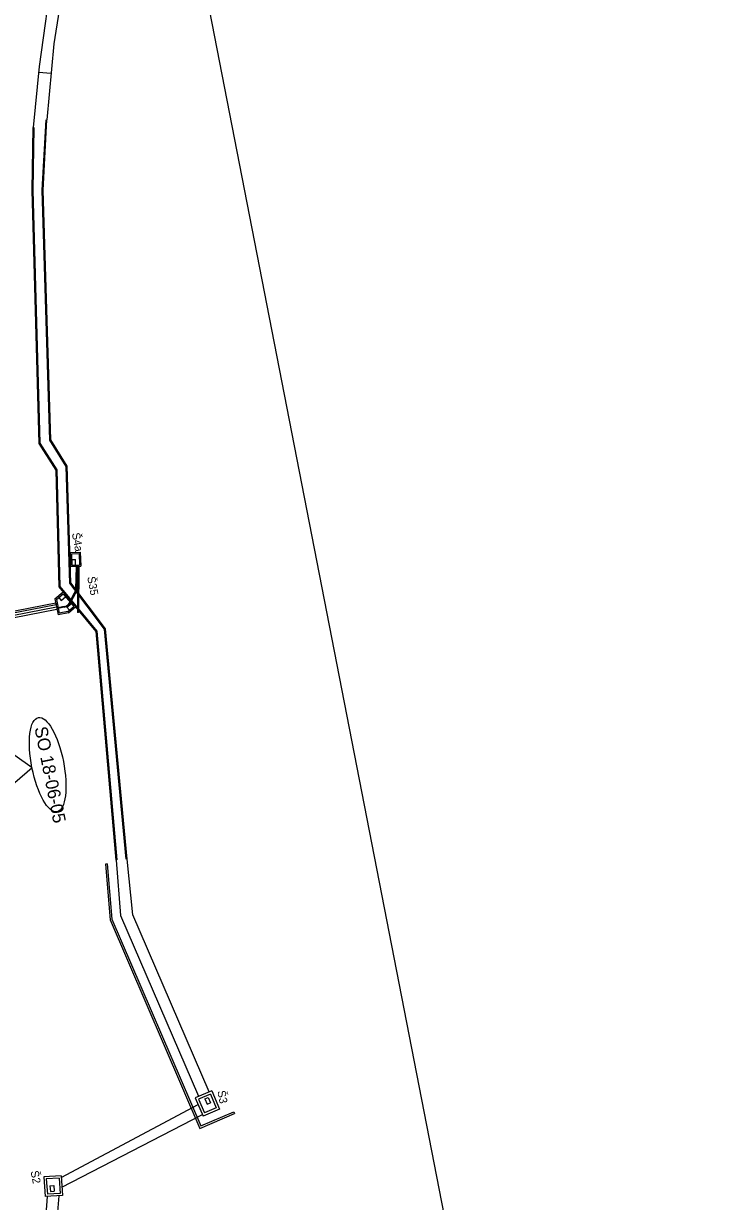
# Model space of a CAD drawing. Extents: x -545258 to -544992, y -1122311 to -1121664.
# Drawn here: x -545101.7 to -544992, y -1122054.6 to -1121870.6 of the extents above; entities that cross this region are included whole.
import ezdxf

# ---------------------------------------------------------------- set-up
doc = ezdxf.new("R2010")
doc.units = 0
for name, color, linetype in [('SO18-15-08_def', 7, 'Continuous'), ('SO18-15-15', 7, 'Continuous'), ('SOPS', 7, 'Continuous'), ('Vrstva 10', 7, 'Continuous')]:
    doc.layers.add(name, color=color, linetype=linetype)

msp = doc.modelspace()

# ---------------------------------------------------------------- linework, layer by layer
at = {"layer": 'SO18-15-08_def'}
for p, q in [((-545097.39, -1121878.4), (-545099.34, -1121878.23)), ((-545094.42, -1121953.24), (-545092.82, -1121953.19)), ((-545094.42, -1121953.24), (-545094.35, -1121955.44)), ((-545094.21, -1121953.44), (-545093.01, -1121953.4)), ((-545094.21, -1121953.44), (-545094.15, -1121955.23)), ((-545094.18, -1121954.33), (-545093.58, -1121954.32)), ((-545094.15, -1121955.23), (-545094.18, -1121954.33)), ((-545093.55, -1121955.21), (-545093.58, -1121954.32)), ((-545093.01, -1121953.4), (-545092.95, -1121955.2)), ((-545092.82, -1121953.19), (-545092.75, -1121955.39)), ((-545094.35, -1121955.44), (-545092.75, -1121955.39)), ((-545094.15, -1121955.23), (-545092.95, -1121955.2)), ((-545094.15, -1121955.23), (-545093.55, -1121955.21)), ((-545093.47, -1121955.41), (-545093.56, -1121958.96)), ((-545093.31, -1121955.41), (-545093.41, -1121959.11)), ((-545093.21, -1121955.4), (-545093.25, -1121962.6)), ((-545093.05, -1121955.4), (-545093.09, -1121962.6)), ((-545096.78, -1121960.48), (-545095.48, -1121959.4)), ((-545096.56, -1121960.56), (-545095.5, -1121959.68)), ((-545096.19, -1121960.25), (-545095.5, -1121959.68)), ((-545095.5, -1121959.68), (-545093.84, -1121961.68)), ((-545095.5, -1121959.68), (-545095.12, -1121960.14)), ((-545095.48, -1121959.4), (-545093.56, -1121961.7)), ((-545094.35, -1121960.75), (-545093.71, -1121959.53)), ((-545094.24, -1121960.88), (-545093.58, -1121959.62)), ((-545093.57, -1121959.11), (-545093.56, -1121958.96)), ((-545096.78, -1121960.48), (-545096.3, -1121962.95)), ((-545096.43, -1121961.29), (-545096.62, -1121961.33)), ((-545096.56, -1121960.56), (-545096.14, -1121962.71)), ((-545096.35, -1121961.68), (-545096.54, -1121961.72)), ((-545096.31, -1121961.86), (-545096.51, -1121961.9)), ((-545095.37, -1121961.68), (-545096.31, -1121961.86)), ((-545095.35, -1121961.78), (-545096.29, -1121961.97)), ((-545096.19, -1121960.25), (-545095.81, -1121960.72)), ((-545095.81, -1121960.72), (-545095.12, -1121960.14)), ((-545094.91, -1121961.79), (-545094.22, -1121961.22)), ((-545094.91, -1121961.79), (-545094.53, -1121962.25)), ((-545094.86, -1121960.45), (-545094.78, -1121960.38)), ((-545094.78, -1121960.38), (-545094.77, -1121960.24)), ((-545094.76, -1121962.44), (-545093.84, -1121961.68)), ((-545094.67, -1121962.63), (-545093.56, -1121961.7)), ((-545094.53, -1121962.25), (-545093.84, -1121961.68)), ((-545094.41, -1121960.99), (-545094.4, -1121960.84)), ((-545094.4, -1121960.84), (-545094.32, -1121960.78)), ((-545094.22, -1121961.22), (-545093.84, -1121961.68)), ((-545093.9, -1121961.6), (-545093.75, -1121961.47)), ((-545096.29, -1121961.97), (-545096.49, -1121962)), ((-545094.67, -1121962.63), (-545096.3, -1121962.95)), ((-545094.76, -1121962.44), (-545096.14, -1121962.71)), ((-545093.09, -1121962.6), (-545093.25, -1121962.6)), ((-545084.6, -1122009.84), (-545085.5, -1122001.11)), ((-545085.5, -1122001.11), (-545085.5, -1122001.11)), ((-545072.67, -1122037.48), (-545084.6, -1122009.84)), ((-545072.28, -1122037.32), (-545074.86, -1122038.41)), ((-545072.28, -1122037.32), (-545071.07, -1122040.17)), ((-545074.86, -1122038.41), (-545073.65, -1122041.26)), ((-545072.49, -1122037.84), (-545074.33, -1122038.62)), ((-545074.33, -1122038.62), (-545073.44, -1122040.74)), ((-545073.37, -1122038.59), (-545072.82, -1122038.36)), ((-545073.37, -1122038.59), (-545073.02, -1122039.42)), ((-545073.02, -1122039.42), (-545072.47, -1122039.19)), ((-545072.82, -1122038.36), (-545072.47, -1122039.19)), ((-545072.49, -1122037.84), (-545071.6, -1122039.96)), ((-545095.8, -1122050.87), (-545074.41, -1122039.46)), ((-545095.69, -1122052.37), (-545073.75, -1122041.03)), ((-545071.07, -1122040.17), (-545073.65, -1122041.26)), ((-545071.6, -1122039.96), (-545073.44, -1122040.74)), ((-545095.82, -1122050.58), (-545098.51, -1122050.76)), ((-545098.51, -1122050.76), (-545098.3, -1122053.85)), ((-545096.14, -1122050.95), (-545098.14, -1122051.09)), ((-545098.14, -1122051.09), (-545097.97, -1122053.48)), ((-545097.57, -1122052.15), (-545096.97, -1122052.11)), ((-545096.97, -1122052.11), (-545096.9, -1122053.01)), ((-545096.14, -1122050.95), (-545095.98, -1122053.34)), ((-545095.82, -1122050.58), (-545095.61, -1122053.67)), ((-545100.26, -1122081.79), (-545097.93, -1122053.83)), ((-545096.16, -1122053.71), (-545098.5, -1122081.93)), ((-545095.61, -1122053.67), (-545098.3, -1122053.85)), ((-545095.98, -1122053.34), (-545097.97, -1122053.48)), ((-545097.57, -1122052.15), (-545097.5, -1122053.05)), ((-545097.5, -1122053.05), (-545096.9, -1122053.01))]:
    msp.add_line(p, q, dxfattribs=at)
for points in [[(-545097.14, -1121861.93), (-545099.25, -1121877.31), (-545100.17, -1121886.86)], [(-545095.16, -1121862.22), (-545096.97, -1121873.75)], [(-545096.97, -1121873.75), (-545098.03, -1121885.66)], [(-545085.65, -1122001.13), (-545089.06, -1121965.23), (-545094.44, -1121958.03), (-545095.03, -1121939.82), (-545097.57, -1121935.68), (-545098.8, -1121896.62), (-545098.18, -1121885.64)], [(-545085.5, -1122001.11), (-545088.91, -1121965.17), (-545094.3, -1121957.98), (-545094.88, -1121939.77), (-545097.42, -1121935.63), (-545098.65, -1121896.62), (-545098.03, -1121885.65)], [(-545087.24, -1122001.27), (-545090.32, -1121965.56), (-545096.11, -1121958.59), (-545096.58, -1121940.38), (-545099.26, -1121936.18), (-545100.35, -1121896.61), (-545100.17, -1121886.86)], [(-545087.09, -1122001.26), (-545090.17, -1121965.5), (-545095.96, -1121958.54), (-545096.43, -1121940.34), (-545099.11, -1121936.13), (-545100.2, -1121896.61), (-545100.02, -1121886.86)], [(-545142.86, -1121970.08), (-545140.57, -1121969.64), (-545138.61, -1121969.26), (-545136.65, -1121968.87), (-545134.68, -1121968.49), (-545132.72, -1121968.11), (-545096.67, -1121961.08)], [(-545142.81, -1121970.33), (-545140.53, -1121969.89), (-545138.56, -1121969.5), (-545136.6, -1121969.12), (-545134.64, -1121968.74), (-545132.67, -1121968.35), (-545130.71, -1121967.97), (-545096.62, -1121961.33)], [(-545142.73, -1121970.72), (-545142.41, -1121970.66), (-545140.45, -1121970.28), (-545138.49, -1121969.89), (-545136.52, -1121969.51), (-545134.56, -1121969.13), (-545132.6, -1121968.75), (-545096.54, -1121961.72)], [(-545142.67, -1121971.07), (-545140.38, -1121970.62), (-545138.42, -1121970.24), (-545136.46, -1121969.86), (-545134.49, -1121969.47), (-545132.53, -1121969.09), (-545096.47, -1121962.06)], [(-545087.24, -1122001.27), (-545086.52, -1122009.91), (-545074.34, -1122038.17)]]:
    msp.add_lwpolyline(points, dxfattribs=at)
for centre, radius, start, end in [((-545094.28, -1121959.09), 0.714, 322.4244, 358.6169), ((-545094.39, -1121959.05), 0.983, 325.0782, 356.8472), ((-545095.64, -1121960.32), 1.38, 281.0281, 329.566), ((-545095.64, -1121960.32), 1.49, 281.0281, 329.9469)]:
    msp.add_arc(centre, radius, start, end, dxfattribs=at)
at = {"layer": 'SO18-15-15'}
for p, q in [((-545088.61, -1122001.86), (-545088.9, -1122001.89)), ((-545074.14, -1122043.19), (-545068.72, -1122040.86)), ((-545073.98, -1122042.8), (-545068.84, -1122040.58)), ((-545068.84, -1122040.58), (-545068.72, -1122040.86))]:
    msp.add_line(p, q, dxfattribs=at)
for points in [[(-545088.9, -1122001.89), (-545088.18, -1122010.62), (-545074.14, -1122043.19)], [(-545088.61, -1122001.86), (-545087.9, -1122010.5), (-545073.98, -1122042.8)]]:
    msp.add_lwpolyline(points, dxfattribs=at)
at = {"layer": 'SOPS'}
for q in [(-545195.93, -1121919.38), (-545175.79, -1122052.14)]:
    msp.add_line((-545100.37, -1121986.85), q, dxfattribs=at)
msp.add_ellipse((-545097.92, -1121986.36), major_axis=(1.46, -7.36), ratio=0.333355, dxfattribs=at)
at = {"layer": 'Vrstva 10'}
msp.add_line((-545112.53, -1121664.03), (-544992.02, -1122282.4), dxfattribs=at)

# ---------------------------------------------------------------- texts
at = {"layer": 'SO18-15-08_def'}
for s, rotation, p in [('Š4a', 280.4462, (-545094.14, -1121950.25)), ('Š35', 280.4462, (-545091.75, -1121957.08)), ('Š3', 281.0281, (-545071.41, -1122037.39)), ('Š2', 281.0281, (-545100.6, -1122049.91))]:
    msp.add_text(s, height=1.25, rotation=rotation, dxfattribs=at).set_placement(p)
at = {"layer": 'SOPS'}
msp.add_text('SO 18-06-05', height=2, rotation=281.252, dxfattribs=at).set_placement((-545099.99, -1121980.62))

doc.saveas('drawing.dxf')
